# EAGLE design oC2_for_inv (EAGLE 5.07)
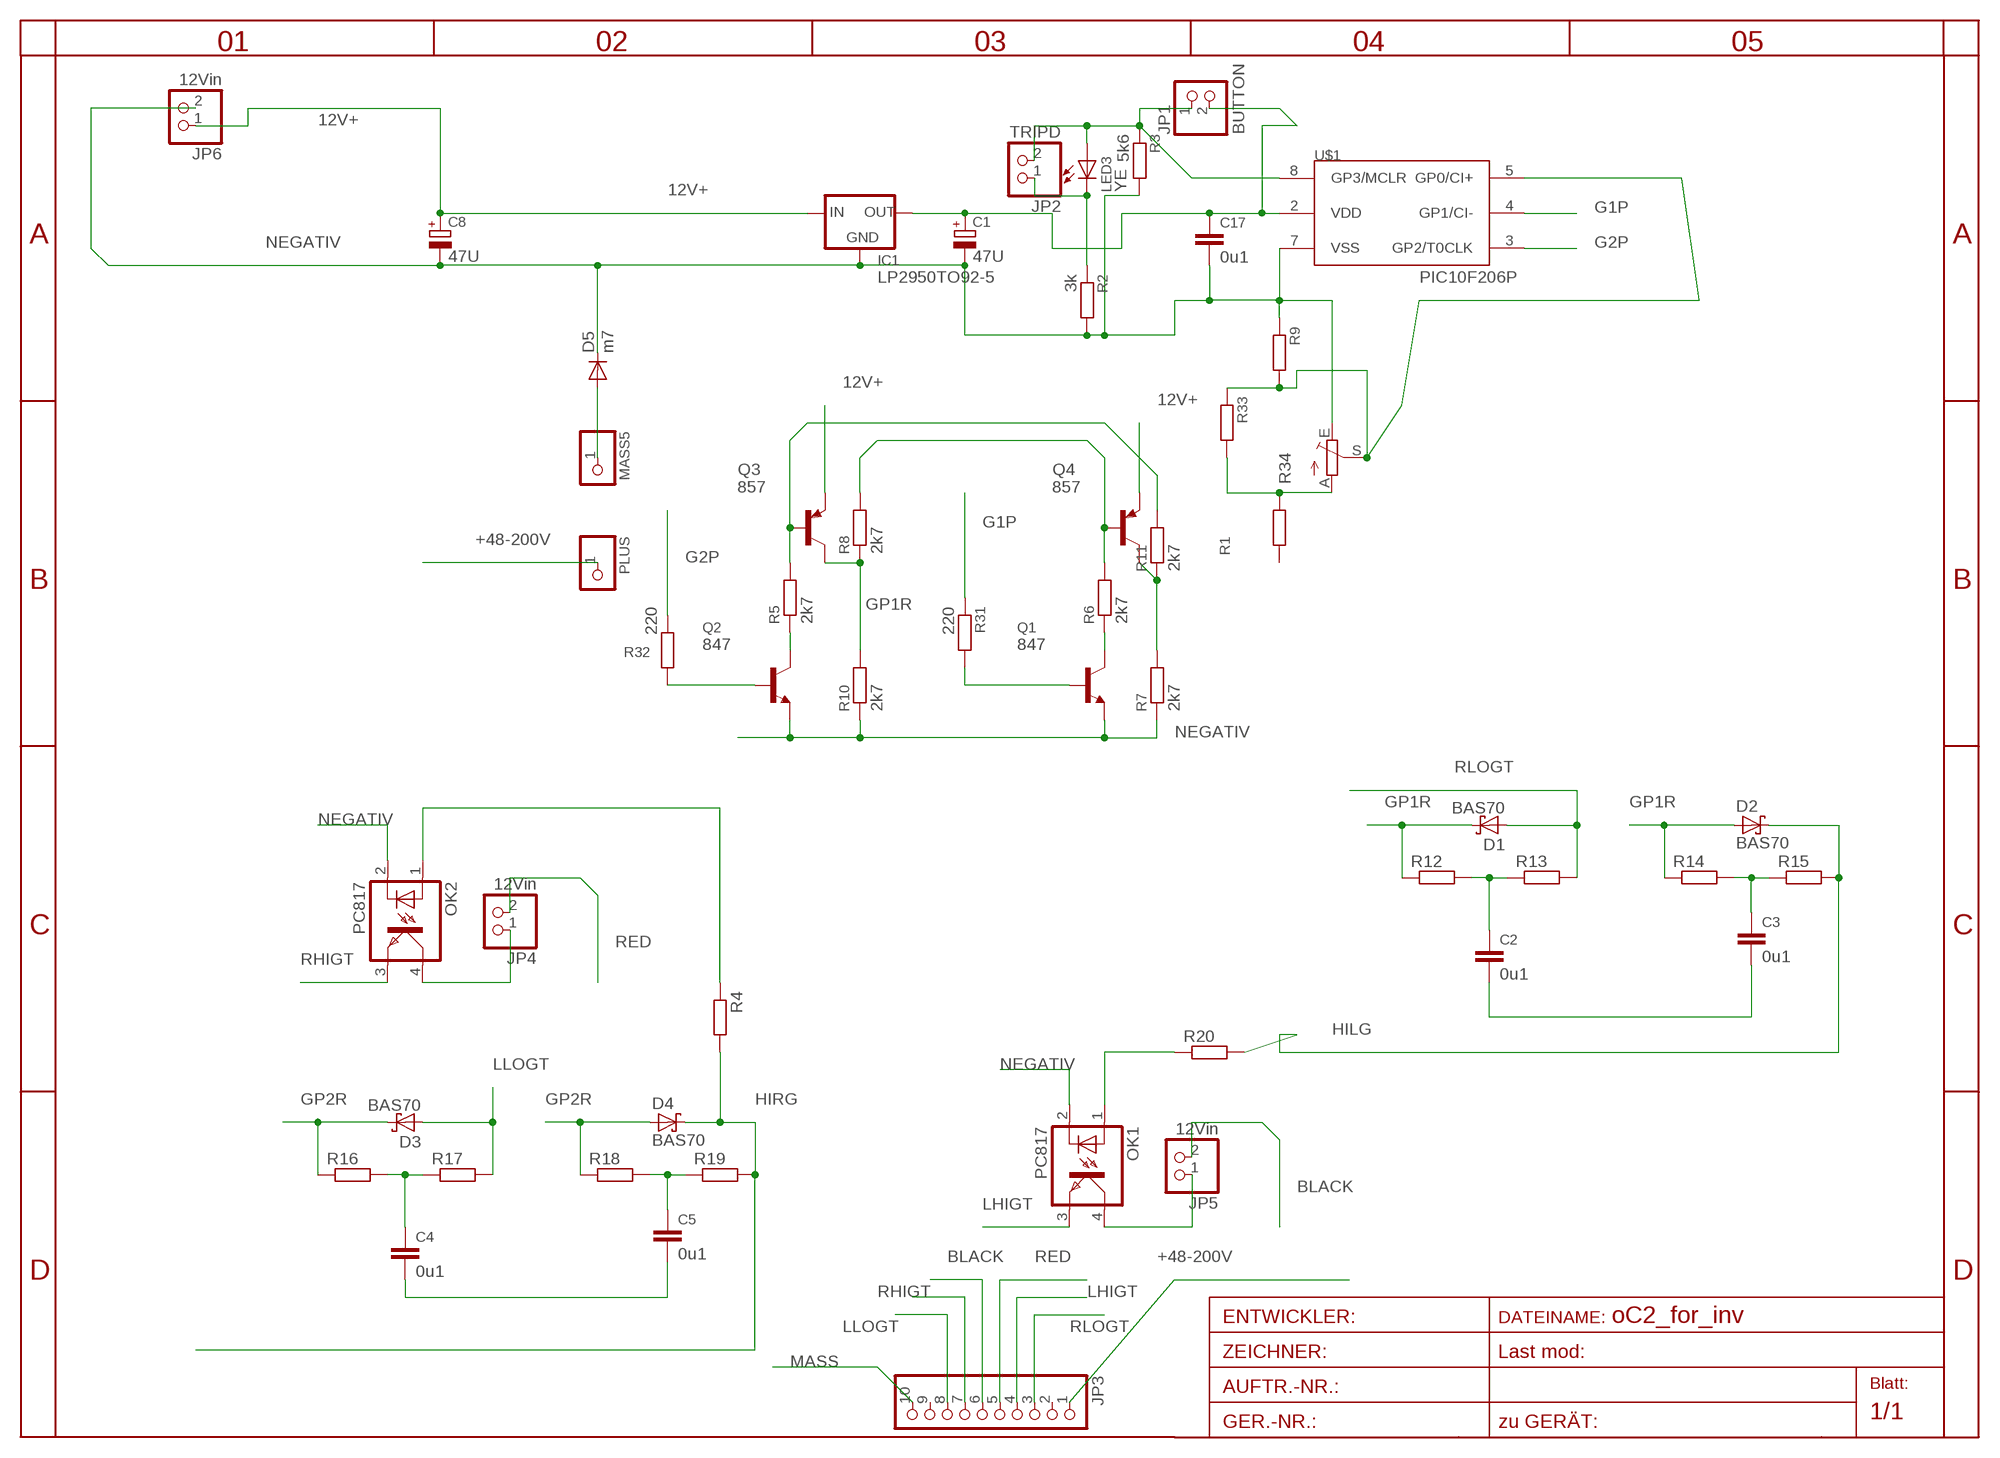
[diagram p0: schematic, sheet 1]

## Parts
C1  47U  CPOL-EUE5-6  [E5-6]
C2  0u1  C-EUC1206  [C1206]
C3  0u1  C-EUC1206  [C1206]
C4  0u1  C-EUC1206  [C1206]
C5  0u1  C-EUC1206  [C1206]
C8  47U  CPOL-EUE5-5  [E5-5]
C17  0u1  C-EUC1206  [C1206]
D1  BAS70  [SOT23]
D2  BAS70  [SOT23]
D3  BAS70  [SOT23]
D4  BAS70  [SOT23]
D5  m7  DIODE-SMA-DO214  [SMA-DO214AC]
IC1  LP2950TO92-5  [T092-5]
JP1  BUTTON  PINHD-1X2/90  [1X02/90]
JP2  TRIPD  PINHD-1X2/90  [1X02/90]
JP3  PINHD-1X10  [1X10WIDE]
JP4  12Vin  PINHD-1X2STR  [1X02]
JP5  12Vin  PINHD-1X2STR  [1X02]
JP6  12Vin  PINHD-1X2STR  [1X02]
LED3  YE  LEDCHIPLED_1206  [CHIPLED_1206]
MASS5  PINHD-1X11MM6  [1X1MM8]
OK1  PC817  [DIL04]
OK2  PC817  [DIL04]
PLUS  PINHD-1X11MM6  [1X1MM8]
Q1  847  BC847ALT1SMD  [SOT23]
Q2  847  BC847ALT1SMD  [SOT23]
Q3  857  BC857ALT1SMD  [SOT23-BEC]
Q4  857  BC857ALT1SMD  [SOT23-BEC]
R1  R-EU_0207/10  [0207/10]
R2  3k  R-EU_R0805  [R0805]
R3  5k6  R-EU_R0805  [R0805]
R4  R-EU_R1206  [R1206]
R5  2k7  R-EU_R0805  [R0805]
R6  2k7  R-EU_R0805  [R0805]
R7  2k7  R-EU_R0805  [R0805]
R8  2k7  R-EU_R0805  [R0805]
R9  R-EU_R0805  [R0805]
R10  2k7  R-EU_R0805  [R0805]
R11  2k7  R-EU_R0805  [R0805]
R12  R-EU_R0805  [R0805]
R13  R-EU_R0805  [R0805]
R14  R-EU_R0805  [R0805]
R15  R-EU_R0805  [R0805]
R16  R-EU_R0805  [R0805]
R17  R-EU_R0805  [R0805]
R18  R-EU_R0805  [R0805]
R19  R-EU_R0805  [R0805]
R20  R-EU_R0805  [R0805]
R31  220  R-EU_R1206  [R1206]
R32  220  R-EU_R1206  [R1206]
R33  R-EU_R0805  [R0805]
R34  TRIM_EU-S64W  [S64W]
U$1  PIC10F206P  [DIL8]

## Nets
12V+: C8.+ IC1.3(IN) JP6.1 Q3.E Q4.E
+48-200V: JP3.1 PLUS.1
BLACK: JP3.6 JP5.2
G1P: R31.1 U$1.4(GP1/CI-)
G2P: R32.1 U$1.3(GP2/T0CLK)
GP1R: D1.3(C) D2.1(A) Q3.C R8.1 R10.2 R12.1 R14.1
GP2R: D3.3(C) D4.1(A) Q4.C R7.2 R11.1 R16.1 R18.1
GP3: JP1.1 JP2.2 LED3.A R3.1 U$1.8(GP3/MCLR)
HILG: D2.3(C) R15.2 R20.2
HIRG: D4.3(C) R4.2 R19.2
LHIGT: JP3.4 OK1.3(EMIT)
LLOGT: D3.1(A) JP3.8 R17.2
MASS: D5.A JP3.10 MASS5.1
N$1: R9.2 R33.1 R34.S U$1.5(GP0/CI+)
N$2: Q2.1(B) R32.2
N$3: C3.1 R14.2 R15.1
N$4: Q2.3(C) R5.1
N$5: Q3.B R5.2 R11.2
N$6: Q1.1(B) R31.2
N$7: JP5.1 OK1.4(COL)
N$8: C5.1 R18.2 R19.1
N$9: Q4.B R6.2 R8.2
N$11: Q1.3(C) R6.1
N$12: C2.1 R12.2 R13.1
N$13: OK2.1(A) R4.1
N$14: JP4.1 OK2.4(COL)
N$15: JP2.1 LED3.C R2.1
N$16: C4.1 R16.2 R17.1
N$17: OK1.1(A) R20.1
N$42: R1.1 R33.2 R34.A
NEGATIV: C1.- C2.2 C3.2 C4.2 C5.2 C8.- C17.2 D5.K(C) IC1.2(GND) JP6.2 OK1.2(C) OK2.2(C) Q1.2(E) Q2.2(E) R2.2 R3.2 R7.1 R9.1 R10.1 R34.E U$1.7(VSS)
RED: JP3.5 JP4.2
RHIGT: JP3.7 OK2.3(EMIT)
RLOGT: D1.1(A) JP3.3 R13.2
VDD: C1.+ C17.1 IC1.1(OUT) JP1.2 U$1.2(VDD)
Unconnected: JP3.2 JP3.9 R1.2

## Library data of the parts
C1 C8 = rcl-2:CPOL-EU: POLARIZED CAPACITOR, European symbol
C2-C5 C17 = rcl-2:C-EU: CAPACITOR, European symbol
D1-D4 = diode:BAS70: Silicon Schottky Diodes
D5 = diode:DIODE-: DIODE
IC1 = v-reg:LP2950?*: Source: http://cache.national.com/ds/LP/LP2950.pdf
JP1 JP2 JP4-JP6 = pinhead:PINHD-1X2: PIN HEADER
JP3 = pinhead:PINHD-1X10: PIN HEADER
LED3 = led:LED: LED
MASS5 PLUS = pinhead:PINHD-1X1: PIN HEADER
OK1 OK2 = optocoupler:PC817: SHARP OPTO COUPLER
Q1 Q2 = transistor-npn:BC847*: NPN Transistor
Q3 Q4 = transistor-pnp:BC857*: PNP Transistror
R1-R3 R5-R11 R31-R33 = rcl-2:R-EU_: RESISTOR, European symbol
R4 R12-R20 = rcl:R-EU_: RESISTOR, European symbol
R34 = pot:TRIM_EU-: POTENTIOMETER
U$1 = microchip-5:PIC10F2*: uPC nW 0,25/0,5k Program Flash memory Comparator

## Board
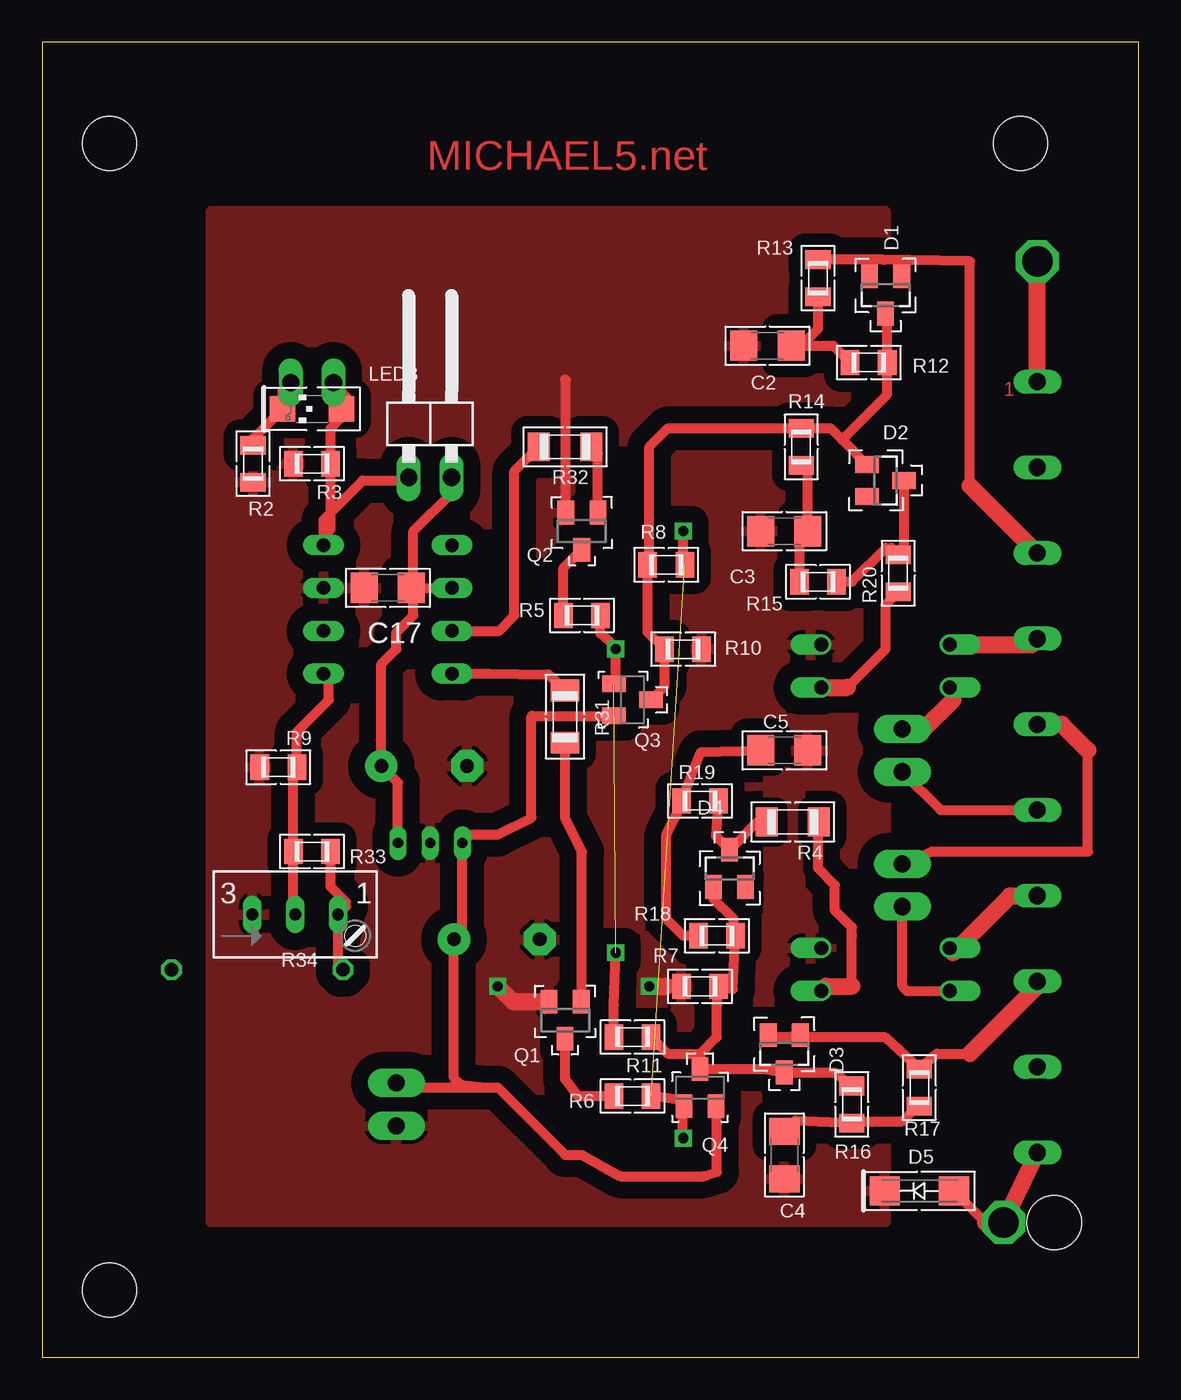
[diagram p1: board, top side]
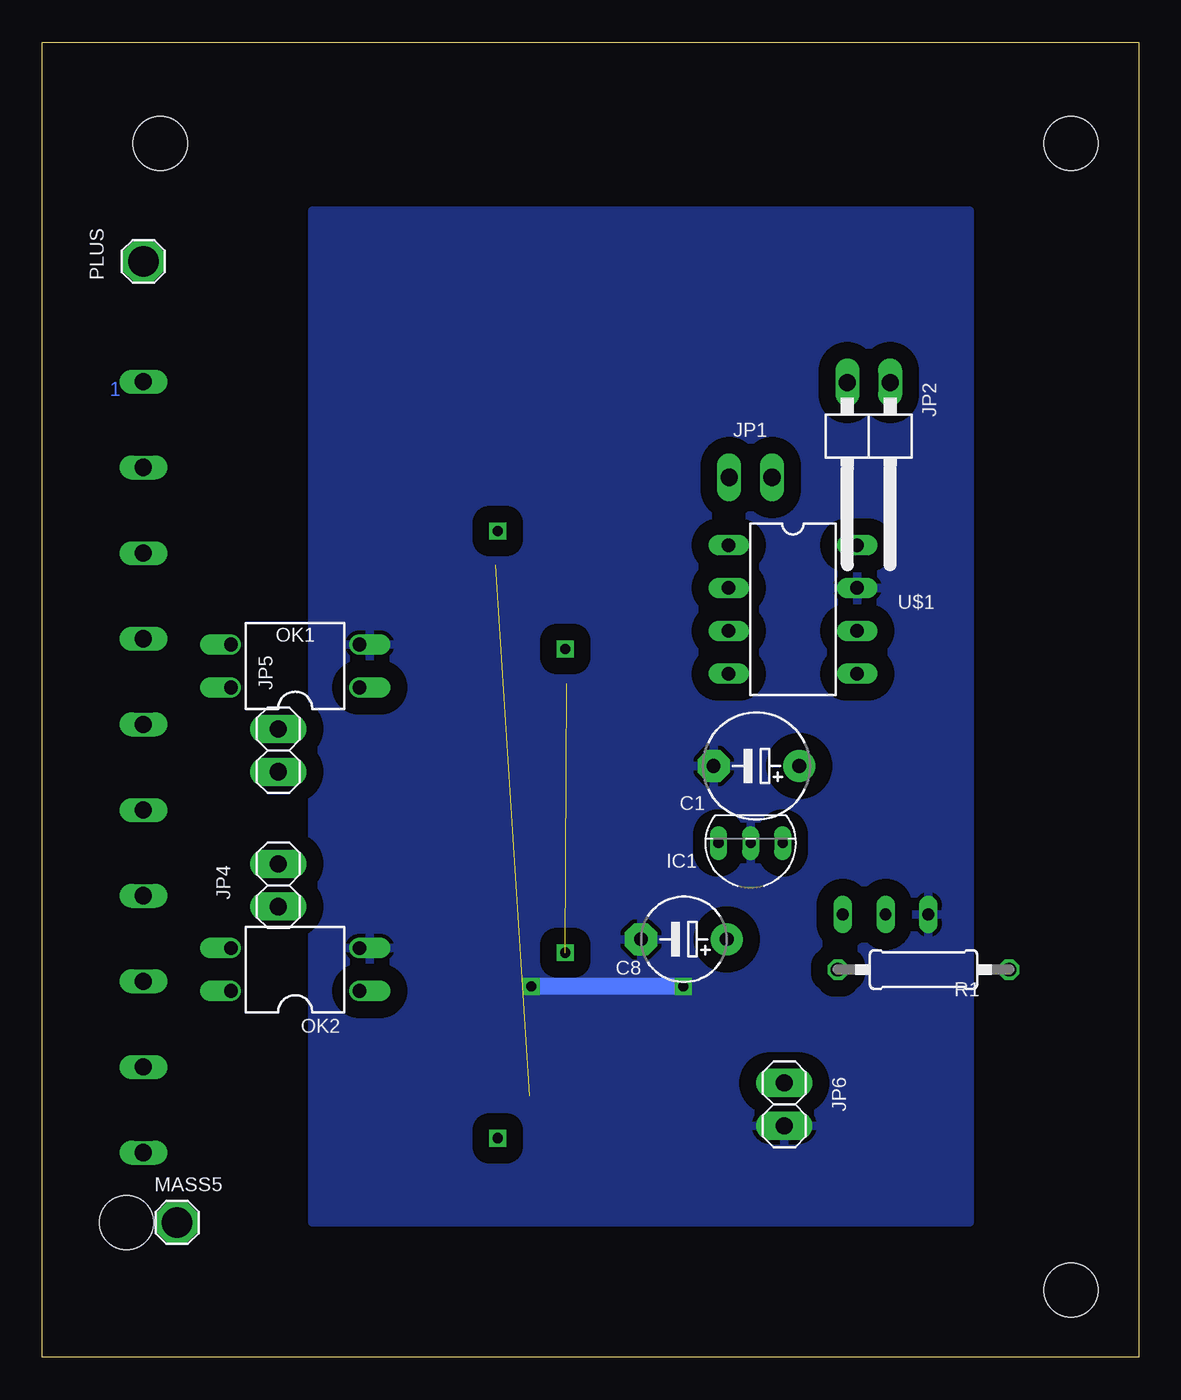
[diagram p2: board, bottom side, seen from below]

Size 65 x 78 mm. Coordinates in mm from the lower left corner, seen from the top.
Outline: 0,0 65,0 65,78 0,78 0,0
Copper layers (1*16): Top 0.035mm / dielectric 1.5mm / Bottom 0.035mm
Design rules "default *": minimum track width 12mil, minimum drill 24mil, track to track 8mil, track to pad 8mil, pad to pad 8mil, via to via 8mil, smd to smd 8mil, copper to edge 40mil, drill to drill 8mil, minimum pad ring 8mil, minimum via ring 8mil, stop-mask expansion 4mil, vias tented up to drill 0mil, thermal gap 10mil
Holes 3.2 mm at 4,72 4,4 58,72 60,8

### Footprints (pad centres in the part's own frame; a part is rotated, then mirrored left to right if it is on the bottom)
E5-6 = drill 0.813 pad 1.905 round: + -2.54,0 | drill 0.813 pad 1.905 octagon: - 2.54,0
C1206 = smd 1.6 x 1.8: 1 -1.4,0; 2 1.4,0
E5-5 = drill 0.813 pad 1.905 round: + -2.54,0 | drill 0.813 pad 1.905 octagon: - 2.54,0
SOT23 = smd 1 x 1.4: 1 -0.95,-1.1; 2 0.95,-1.1; 3 0,1.1
SMA-DO214AC = smd 1.8 x 1.7: A 2.05,-0.127; K -2.05,-0.127
T092-5 = drill 0.6 pad 0.813 long: 1 -1.905,0; 2 0,0; 3 1.905,0
1X02/90 = drill 1.016 long: 1 -1.27,-3.81; 2 1.27,-3.81
1X10WIDE = drill 1.016 long: 1 -22.86,0; 2 -17.78,0; 3 -12.7,0; 4 -7.62,0; 5 -2.54,0; 6 2.54,0; 7 7.62,0; 8 12.7,0; 9 17.78,0; 10 22.86,0
1X02 = drill 1.016 pad 1.676 long: 1 -1.27,0; 2 1.27,0
CHIPLED_1206 = smd 1.5 x 1.5: A 0,-1.75; C 0,1.75
1X1MM8 = drill 1.8 pad 2.54 octagon: 1 0,0
DIL04 = drill 0.813 offset: 1 -1.27,-3.81; 2 1.27,-3.81; 3 1.27,3.81; 4 -1.27,3.81
SOT23-BEC = smd 1 x 1.4: B -0.95,-1.1; C 0,1.1; E 0.95,-1.1
0207/10 = drill 0.813 octagon: 1 -5.08,0; 2 5.08,0
R0805 = smd 1.1 x 1.5: 1 -1.1,0; 2 1.1,0
R1206 = smd 1.3 x 1.7: 1 -1.55,0; 2 1.55,0
S64W = drill 0.7 long: A 2.54,1.27; E -2.54,1.27; S 0,1.27
DIL8 = drill 0.8 long: 1 -3.81,-3.81; 2 -1.27,-3.81; 3 1.27,-3.81; 4 3.81,-3.81; 5 3.81,3.81; 6 1.27,3.81; 7 -1.27,3.81; 8 -3.81,3.81

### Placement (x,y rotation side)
C1  22.65,35.07 180 bottom
C2  43,60 180 top
C3  44,49 180 top
C4  44,12 270 top
C5  44,36 0 top
C8  26.95,24.8 180 bottom
C17  20.49,45.63 180 top
D1  50,63 180 top
D2  50,52 270 top
D3  44,18 180 top
D4  40.75,29 0 top
D5  52,10 0 top
IC1  23,30.5 180 bottom
JP1  23,56 0 top
JP2  16,54 180 bottom
JP3  59,35 270 bottom
JP4  51,28 90 bottom
JP5  51,36 270 bottom
JP6  21,15 270 bottom
LED3  16,56.25 90 top
MASS5  57,8 0 bottom
OK1  50,41 90 bottom
OK2  50,23 90 bottom
PLUS  59,65 180 bottom
Q1  31,20 180 top
Q2  32,49 180 top
Q3  35,39 270 top
Q4  39,16 0 top
R1  12.75,23 0 bottom
R2  12.5,53 270 top
R3  16,53 180 top
R4  44.5,31.75 180 top
R5  32,44 0 top
R6  35,15.5 0 top
R7  39,22 0 top
R8  37,47 0 top
R9  14,35 0 top
R10  38,42 180 top
R11  35,19 180 top
R12  49,59 180 top
R13  46,64 90 top
R14  45,54 270 top
R15  46,46 0 top
R16  48,15 270 top
R17  52,16 90 top
R18  40,25 180 top
R19  39,33 0 top
R20  50.75,46.5 90 top
R31  31,38 270 top
R32  31,54 0 top
R33  16,30 0 top
R34  15,25 0 top
U$1  20.49,44.36 270 bottom

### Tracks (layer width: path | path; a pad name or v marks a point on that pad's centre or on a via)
12V+
  Top 0.6: JP6.1 21.73,16.27 22,16 25,16 | 25,16 26,16 | 26,16 27,16 31,12 32,12 34.25,10.75 39.25,10.75 40,11 40,13.85 Q4.E | 26,16 24.59,16.16 | Q3.E 29.05,38.05 29,38 29,32 27,31 25.41,31 IC1.3 24.91,25.29 C8.+ 24.41,16.59 25,16
+48-200V
  Top 1: JP3.1 PLUS.1
BLACK
  Top 0.6: JP3.6 53.27,32.46 JP5.2
G1P
  Top 0.6: U$1.4 26.45,40.55 30,40.5 R31.1
G2P
  Top 0.6: U$1.3 27.09,43.09 28,44 28,52.55 R32.1
GP1R
  Top 0.6: 47.42,54.42 46.75,55.1 R14.1 37.1,55.1 36,54 36,47.1 R8.1 35.9,43 R10.2 36.9,39.8 Q3.C | 47.42,54.42 D2.1 | D1.3 50.1,61.8 R12.1 50.1,57.1 47.42,54.42
GP2R
  Top 0.6: 39,18 Q4.C 42.8,17.1 D3.3 46.95,16.9 R16.1 | 39,18 40,19 40,20.9 R7.2 40.95,21.85 R18.1 41,25.05 41,26 39.8,27.2 D4.1 | 39,18 37.1,18 R11.1
GP3
  Top 0.6: U$1.8 16.68,49 | 16.68,49 16.68,49.68 19,52 21.54,52 JP1.1 | 16.68,49 17,49 17.1,49.1 R3.1 17.1,55.1 18,56 LED3.A 18,56.5 18,57 17.27,57.73 JP2.2
HILG
  Top 0.6: R15.2 48,46 50,48 50.35,48 R20.2 51,47.85 51,48 51.1,48.1 D2.3
HIRG
  Top 0.6: R19.2 39.95,30.9 D4.3 42.4,31.75 R4.2
LHIGT
  Top 0.6: 58.65,42.27 JP3.4
  Top 1: OK1.3 58.65,42.27
LLOGT
  Top 0.6: 59,22 JP3.8 | 55,18 53.05,18 R17.2 49.95,19 43,19 42.9,18.9 D3.1
  Top 1: 55,18 59,22
MASS
  Top 0.6: D5.A 55.92,8
  Top 1: JP3.10 MASS5.1 55.92,8
N$1
  Top 0.6: R34.S 14.9,26.27 R33.1 14.9,34.8 R9.2 15.1,37.1 17,39 17,40.23 U$1.5
N$2
  Top 0.6: Q2.1 32.95,53.6 R32.2
N$3
  Top 0.6: R15.1 44.9,48.5 C3.1 45.4,52.5 R14.2
N$4
  Top 0.6: R5.1 30.9,46.8 Q2.3
N$5  (via drill 0.6)  (1 unrouted)
  Top 0.6: 33.1,43 33.1,42.9 | 33.1,43 R5.2 | Q3.B 34,40.05 v34,42 34,42.1 33.1,43 | R11.2 33.9,20.9 v34,24
N$6
  Top 0.6: R31.2 31,32 32,30 32,21.15 Q1.1
N$7
  Top 0.6: JP5.1 52.27,37.27 | 54,39 54,39.54
  Top 1: 52.27,37.27 54,39 | 54,39.54 OK1.4
N$8
  Top 0.6: R18.2 38,25 37,26 37,31 38,33 R19.1 39.05,35.9 C5.1
N$9  (via drill 0.6)  (1 unrouted)
  Top 0.6: 37.95,15.25 R6.2 | Q4.B 37.95,15.25 | 37.95,15.25 37.95,13.05 v38,13 | v38,49 38,47.1 R8.2
N$11
  Top 0.6: R6.1 31.75,15.5 31,16.5 Q1.3
N$12
  Top 0.6: R13.1 46,61 45,60 C2.1 46.9,60 R12.2
N$13
  Top 0.6: 48,22 48,25 48,25.5 47,26.5 47,28 46,29 46,31.7 R4.1 | OK2.1 46.46,22
  Top 1: 46.46,22 48,22
N$14
  Top 0.6: OK2.4 51.27,21.73 51,22 JP4.1
N$15
  Top 0.6: R2.1 12.5,54.5 LED3.C 14.25,57.33 JP2.1
N$16
  Top 0.6: R17.1 52,15 51,14 48.05,14 R16.2 44.65,14.05 C4.1
N$17
  Top 0.6: 47.73,39.73 50,42 50,44.65 R20.1
  Top 1: OK1.1 47.73,39.73
N$42
  Top 0.6: R33.2 17.1,27.9 18,27 18,26.73 R34.A 17.54,23.29 R1.1
NEGATIV  (via drill 0.6)
  Top 0.6: Q2.2 31.05,57.95 31,58
  Top 1: Q1.2 27.9,21.1 v27,22 | v36,22 37,22
  Bottom 1: v27,22 v36,22
  pour Top (isolate 1): 10,68 50,68 50,8 10,8
  pour Bottom (isolate 1): 10,68 49,68 49,8 10,8
  pour Top (isolate 0.6): 43,35 43,24 47,24 47,25 45,25 45,35
RED
  Top 0.6: 62,36 62,30 52.73,30 JP4.2
  Top 1: JP3.5 60.46,37.54 62,36
RHIGT
  Top 0.6: 54,24 54,24.08 OK2.3
  Top 1: JP3.7 57.38,27.38 54,24
RLOGT
  Top 0.6: R13.2 49.9,65.1 51.43,65.07 | 51.43,65.07 55,65 55,51.7 | D1.1 50.7,64.85 51.43,65.07
  Top 1: JP3.3 55,51.7
VDD
  Top 0.6: IC1.1 21.09,34.09 C1.+ 20.11,41.11 21,42 21,43 22,44 22,45.52 C17.1 | C17.1 U$1.2 | JP1.2 24.27,51.27 22,49 22,45.74 C17.1

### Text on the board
Top: MICHAEL5.net | 1
Bottom: 1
